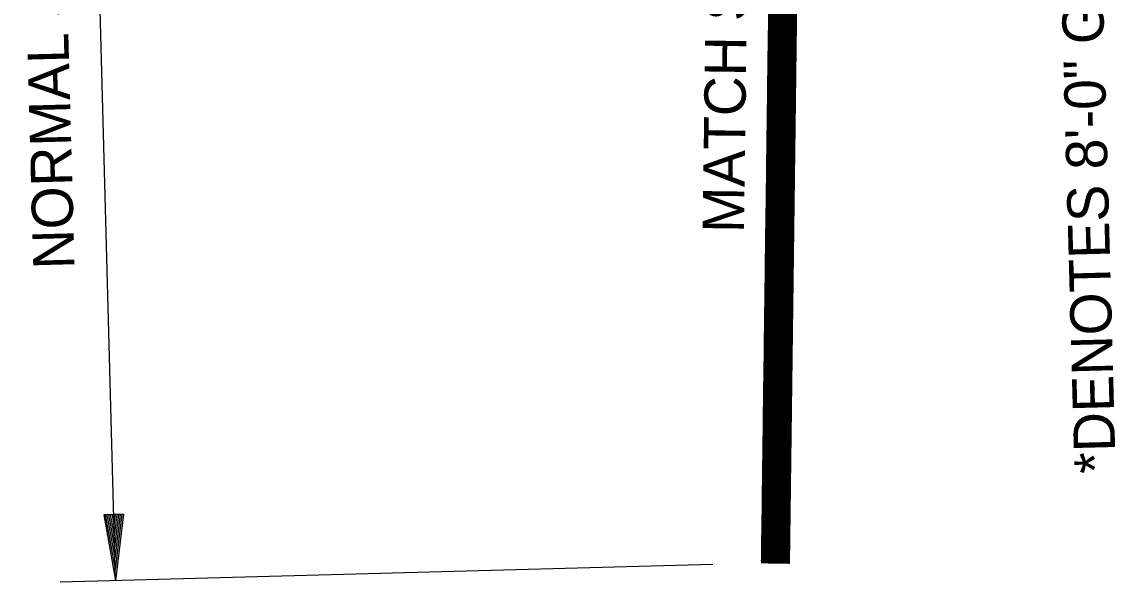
# Model space of a CAD drawing. Extents: x 1929624 to 1935547, y 596315 to 605721.
# Drawn here: x 1932254.7 to 1932413.5, y 600448.6 to 600530 of the extents above; entities that cross this region are included whole.
import ezdxf

# ---------------------------------------------------------------- set-up
doc = ezdxf.new("R2010")
doc.units = 0
doc.layers.add('Default', color=7, linetype='Continuous')
doc.layers.add('R_Draft', color=7, linetype='Continuous')

msp = doc.modelspace()

# ---------------------------------------------------------------- linework, layer by layer
at = {"layer": 'Default'}
for p, q in [((1932365.29, 600687.8), (1932362.18, 600451.38)), ((1932369.13, 600675.3), (1932366.19, 600451.33)), ((1932367.21, 600528.79), (1932365.06, 600608.88)), ((1932367.22, 600529.39), (1932365.08, 600608.9)), ((1932366.92, 600507.17), (1932364.23, 600607.39)), ((1932366.93, 600507.77), (1932364.24, 600607.99)), ((1932366.94, 600508.37), (1932364.26, 600608.04)), ((1932366.95, 600508.97), (1932364.29, 600608.07)), ((1932366.96, 600509.57), (1932364.31, 600608.09)), ((1932366.96, 600510.17), (1932364.33, 600608.12)), ((1932366.97, 600510.78), (1932364.36, 600608.14)), ((1932366.98, 600511.38), (1932364.38, 600608.17)), ((1932366.99, 600511.98), (1932364.4, 600608.19)), ((1932367, 600512.58), (1932364.43, 600608.21)), ((1932367, 600513.18), (1932364.45, 600608.24)), ((1932367.01, 600513.78), (1932364.47, 600608.26)), ((1932367.02, 600514.38), (1932364.5, 600608.29)), ((1932367.03, 600514.98), (1932364.52, 600608.31)), ((1932367.03, 600515.58), (1932364.54, 600608.34)), ((1932367.04, 600516.18), (1932364.57, 600608.36)), ((1932367.05, 600516.78), (1932364.59, 600608.39)), ((1932367.06, 600517.38), (1932364.61, 600608.41)), ((1932367.07, 600517.98), (1932364.64, 600608.44)), ((1932367.07, 600518.58), (1932364.66, 600608.46)), ((1932367.08, 600519.18), (1932364.68, 600608.49)), ((1932367.09, 600519.78), (1932364.71, 600608.51)), ((1932367.1, 600520.38), (1932364.73, 600608.53)), ((1932367.11, 600520.98), (1932364.76, 600608.56)), ((1932367.11, 600521.59), (1932364.78, 600608.58)), ((1932367.12, 600522.19), (1932364.8, 600608.61)), ((1932367.13, 600522.79), (1932364.83, 600608.63)), ((1932367.14, 600523.39), (1932364.85, 600608.66)), ((1932367.15, 600523.99), (1932364.87, 600608.68)), ((1932367.15, 600524.59), (1932364.9, 600608.71)), ((1932367.16, 600525.19), (1932364.92, 600608.73)), ((1932367.17, 600525.79), (1932364.94, 600608.76)), ((1932367.18, 600526.39), (1932364.97, 600608.78)), ((1932367.18, 600526.99), (1932364.99, 600608.81)), ((1932367.19, 600527.59), (1932365.01, 600608.83)), ((1932367.2, 600528.19), (1932365.04, 600608.86)), ((1932366.91, 600505.97), (1932364.22, 600606.19)), ((1932366.92, 600506.57), (1932364.23, 600606.79)), ((1932268.3, 600448.86), (1932264.1, 600605.33)), ((1932366.89, 600504.17), (1932364.19, 600604.39)), ((1932366.89, 600504.77), (1932364.2, 600604.99)), ((1932366.9, 600505.37), (1932364.21, 600605.59)), ((1932366.86, 600502.37), (1932364.17, 600602.59)), ((1932366.87, 600502.97), (1932364.18, 600603.19)), ((1932366.88, 600503.57), (1932364.19, 600603.79)), ((1932366.85, 600501.77), (1932364.16, 600601.99)), ((1932366.85, 600501.17), (1932364.16, 600601.39)), ((1932366.82, 600499.37), (1932364.13, 600599.58)), ((1932366.83, 600499.97), (1932364.14, 600600.18)), ((1932366.84, 600500.57), (1932364.15, 600600.78)), ((1932366.8, 600497.56), (1932364.11, 600597.78)), ((1932366.81, 600498.77), (1932364.12, 600598.98)), ((1932366.81, 600498.17), (1932364.12, 600598.38)), ((1932366.78, 600496.36), (1932364.09, 600596.58)), ((1932366.79, 600496.96), (1932364.1, 600597.18)), ((1932366.76, 600494.56), (1932364.07, 600594.78)), ((1932366.77, 600495.76), (1932364.08, 600595.98)), ((1932366.77, 600495.16), (1932364.08, 600595.38)), ((1932366.74, 600493.36), (1932364.05, 600593.58)), ((1932366.75, 600493.96), (1932364.06, 600594.18)), ((1932366.72, 600491.56), (1932364.03, 600591.78)), ((1932366.74, 600492.76), (1932364.04, 600592.98)), ((1932366.73, 600492.16), (1932364.04, 600592.38)), ((1932366.7, 600490.36), (1932364.01, 600590.57)), ((1932366.7, 600489.76), (1932364.01, 600589.97)), ((1932366.71, 600490.96), (1932364.02, 600591.18)), ((1932366.68, 600488.56), (1932363.99, 600588.77)), ((1932366.69, 600489.16), (1932364, 600589.37)), ((1932366.66, 600487.36), (1932363.97, 600587.57)), ((1932366.66, 600486.76), (1932363.97, 600586.97)), ((1932366.67, 600487.96), (1932363.98, 600588.17)), ((1932366.63, 600484.95), (1932363.94, 600585.17)), ((1932366.64, 600485.55), (1932363.95, 600585.77)), ((1932366.65, 600486.16), (1932363.96, 600586.37)), ((1932366.62, 600484.35), (1932363.93, 600584.57)), ((1932366.62, 600483.75), (1932363.93, 600583.97)), ((1932366.59, 600481.95), (1932363.9, 600582.17)), ((1932366.6, 600482.55), (1932363.91, 600582.77)), ((1932366.61, 600483.15), (1932363.92, 600583.37)), ((1932366.57, 600480.15), (1932363.88, 600580.37)), ((1932366.59, 600481.35), (1932363.89, 600581.57)), ((1932366.58, 600480.75), (1932363.89, 600580.97)), ((1932366.55, 600478.95), (1932363.86, 600579.17)), ((1932366.56, 600479.55), (1932363.87, 600579.77)), ((1932366.53, 600477.15), (1932363.84, 600577.37)), ((1932366.54, 600477.75), (1932363.85, 600577.97)), ((1932366.55, 600478.35), (1932363.86, 600578.57)), ((1932366.51, 600475.95), (1932363.82, 600576.16)), ((1932366.51, 600475.35), (1932363.82, 600575.56)), ((1932366.52, 600476.55), (1932363.83, 600576.77)), ((1932366.49, 600474.14), (1932363.8, 600574.36)), ((1932366.5, 600474.74), (1932363.81, 600574.96)), ((1932366.47, 600472.94), (1932363.78, 600573.16)), ((1932366.47, 600472.34), (1932363.78, 600572.56)), ((1932366.48, 600473.54), (1932363.79, 600573.76)), ((1932366.44, 600470.54), (1932363.75, 600570.76)), ((1932366.45, 600471.14), (1932363.76, 600571.36)), ((1932366.46, 600471.74), (1932363.77, 600571.96)), ((1932366.43, 600469.34), (1932363.74, 600569.56)), ((1932366.44, 600469.94), (1932363.75, 600570.16)), ((1932366.4, 600467.54), (1932363.71, 600567.76)), ((1932366.41, 600468.14), (1932363.72, 600568.36)), ((1932366.42, 600468.74), (1932363.73, 600568.96)), ((1932366.39, 600466.34), (1932363.7, 600566.56)), ((1932366.4, 600466.94), (1932363.71, 600567.16)), ((1932366.36, 600464.54), (1932363.67, 600564.75)), ((1932366.37, 600465.14), (1932363.68, 600565.35)), ((1932366.38, 600465.74), (1932363.69, 600565.95)), ((1932366.34, 600462.74), (1932363.65, 600562.95)), ((1932366.35, 600463.34), (1932363.66, 600563.55)), ((1932366.36, 600463.94), (1932363.67, 600564.15)), ((1932366.32, 600461.54), (1932363.63, 600561.75)), ((1932366.33, 600462.14), (1932363.64, 600562.35)), ((1932366.3, 600459.73), (1932363.61, 600559.95)), ((1932366.31, 600460.33), (1932363.62, 600560.55)), ((1932366.32, 600460.93), (1932363.63, 600561.15)), ((1932366.28, 600457.93), (1932363.59, 600558.15)), ((1932366.29, 600459.13), (1932363.6, 600559.35)), ((1932366.29, 600458.53), (1932363.6, 600558.75)), ((1932366.26, 600456.73), (1932363.57, 600556.95)), ((1932366.27, 600457.33), (1932363.58, 600557.55)), ((1932366.24, 600454.93), (1932363.55, 600555.15)), ((1932366.25, 600456.13), (1932363.56, 600556.35)), ((1932366.25, 600455.53), (1932363.56, 600555.75)), ((1932366.21, 600453.13), (1932363.52, 600553.34)), ((1932366.22, 600453.73), (1932363.53, 600553.94)), ((1932366.23, 600454.33), (1932363.54, 600554.55)), ((1932366.2, 600451.93), (1932363.51, 600552.14)), ((1932366.21, 600452.53), (1932363.52, 600552.74)), ((1932366.14, 600451.33), (1932363.48, 600550.34)), ((1932366.17, 600451.32), (1932363.49, 600550.94)), ((1932366.19, 600451.33), (1932363.5, 600551.54)), ((1932366.07, 600451.33), (1932363.46, 600548.54)), ((1932366.09, 600451.33), (1932363.47, 600549.14)), ((1932366.12, 600451.33), (1932363.48, 600549.74)), ((1932366.05, 600451.33), (1932363.45, 600547.94)), ((1932366.02, 600451.33), (1932363.45, 600547.34)), ((1932365.95, 600451.33), (1932363.42, 600545.54)), ((1932365.97, 600451.33), (1932363.43, 600546.14)), ((1932366, 600451.33), (1932363.44, 600546.74)), ((1932365.93, 600451.33), (1932363.41, 600544.94)), ((1932365.9, 600451.33), (1932363.41, 600544.34)), ((1932365.83, 600451.33), (1932363.38, 600542.54)), ((1932365.85, 600451.33), (1932363.39, 600543.14)), ((1932365.88, 600451.33), (1932363.4, 600543.74)), ((1932365.76, 600451.33), (1932363.36, 600540.73)), ((1932365.81, 600451.33), (1932363.37, 600541.94)), ((1932365.78, 600451.33), (1932363.37, 600541.34)), ((1932365.71, 600451.33), (1932363.34, 600539.53)), ((1932365.73, 600451.33), (1932363.35, 600540.13)), ((1932365.64, 600451.33), (1932363.32, 600537.73)), ((1932365.69, 600451.33), (1932363.33, 600538.93)), ((1932365.66, 600451.33), (1932363.33, 600538.33)), ((1932365.59, 600451.33), (1932363.3, 600536.53)), ((1932365.57, 600451.33), (1932363.3, 600535.93)), ((1932365.61, 600451.33), (1932363.31, 600537.13)), ((1932365.52, 600451.33), (1932363.28, 600534.73)), ((1932365.54, 600451.33), (1932363.29, 600535.33)), ((1932365.47, 600451.34), (1932363.26, 600533.53)), ((1932365.45, 600451.33), (1932363.26, 600532.93)), ((1932365.49, 600451.34), (1932363.27, 600534.13)), ((1932365.37, 600451.34), (1932363.23, 600531.13)), ((1932365.4, 600451.34), (1932363.24, 600531.73)), ((1932365.42, 600451.34), (1932363.25, 600532.33)), ((1932365.35, 600451.34), (1932363.22, 600530.52)), ((1932365.33, 600451.34), (1932363.22, 600529.92)), ((1932365.25, 600451.34), (1932363.19, 600528.12)), ((1932365.28, 600451.34), (1932363.2, 600528.72)), ((1932365.3, 600451.34), (1932363.21, 600529.32)), ((1932365.18, 600451.34), (1932363.17, 600526.32)), ((1932365.21, 600451.34), (1932363.18, 600526.92)), ((1932365.23, 600451.34), (1932363.19, 600527.52)), ((1932365.13, 600451.34), (1932363.15, 600525.12)), ((1932365.16, 600451.34), (1932363.16, 600525.72)), ((1932365.06, 600451.34), (1932363.13, 600523.32)), ((1932365.09, 600451.34), (1932363.14, 600523.92)), ((1932365.11, 600451.34), (1932363.15, 600524.52)), ((1932365.01, 600451.34), (1932363.11, 600522.12)), ((1932364.99, 600451.34), (1932363.11, 600521.52)), ((1932365.04, 600451.34), (1932363.12, 600522.72)), ((1932364.94, 600451.34), (1932363.09, 600520.32)), ((1932364.97, 600451.34), (1932363.1, 600520.92)), ((1932364.89, 600451.34), (1932363.07, 600519.12)), ((1932364.87, 600451.34), (1932363.07, 600518.52)), ((1932364.92, 600451.34), (1932363.08, 600519.72)), ((1932364.82, 600451.34), (1932363.05, 600517.32)), ((1932364.85, 600451.34), (1932363.06, 600517.92)), ((1932364.75, 600451.34), (1932363.03, 600515.51)), ((1932364.8, 600451.34), (1932363.04, 600516.72)), ((1932364.77, 600451.35), (1932363.04, 600516.11)), ((1932364.68, 600451.35), (1932363, 600513.71)), ((1932364.7, 600451.35), (1932363.01, 600514.31)), ((1932364.73, 600451.35), (1932363.02, 600514.91)), ((1932364.63, 600451.35), (1932362.99, 600512.51)), ((1932364.65, 600451.35), (1932363, 600513.11)), ((1932364.56, 600451.35), (1932362.96, 600510.71)), ((1932364.58, 600451.35), (1932362.97, 600511.31)), ((1932364.61, 600451.35), (1932362.98, 600511.91)), ((1932364.49, 600451.35), (1932362.94, 600508.91)), ((1932364.51, 600451.35), (1932362.95, 600509.51)), ((1932364.53, 600451.35), (1932362.96, 600510.11)), ((1932364.44, 600451.35), (1932362.92, 600507.71)), ((1932364.46, 600451.35), (1932362.93, 600508.31)), ((1932364.37, 600451.35), (1932362.9, 600505.91)), ((1932364.39, 600451.35), (1932362.91, 600506.51)), ((1932364.41, 600451.35), (1932362.92, 600507.11)), ((1932364.29, 600451.35), (1932362.88, 600504.1)), ((1932364.34, 600451.35), (1932362.89, 600505.3)), ((1932364.32, 600451.35), (1932362.89, 600504.7)), ((1932364.25, 600451.35), (1932362.86, 600502.9)), ((1932364.27, 600451.35), (1932362.87, 600503.5)), ((1932364.17, 600451.35), (1932362.84, 600501.1)), ((1932364.22, 600451.35), (1932362.85, 600502.3)), ((1932364.2, 600451.35), (1932362.85, 600501.7)), ((1932364.1, 600451.35), (1932362.81, 600499.3)), ((1932364.13, 600451.35), (1932362.82, 600499.9)), ((1932364.15, 600451.35), (1932362.83, 600500.5)), ((1932364.05, 600451.35), (1932362.8, 600498.1)), ((1932364.08, 600451.35), (1932362.81, 600498.7)), ((1932363.98, 600451.36), (1932362.77, 600496.3)), ((1932364.01, 600451.36), (1932362.78, 600496.9)), ((1932364.03, 600451.35), (1932362.79, 600497.5)), ((1932363.93, 600451.36), (1932362.76, 600495.09)), ((1932363.96, 600451.35), (1932362.77, 600495.7)), ((1932363.89, 600451.36), (1932362.74, 600493.89)), ((1932363.86, 600451.36), (1932362.74, 600493.29)), ((1932363.91, 600451.36), (1932362.75, 600494.49)), ((1932363.79, 600451.36), (1932362.71, 600491.49)), ((1932363.81, 600451.36), (1932362.72, 600492.09)), ((1932363.84, 600451.36), (1932362.73, 600492.69)), ((1932363.77, 600451.36), (1932362.7, 600490.89)), ((1932363.74, 600451.36), (1932362.7, 600490.29)), ((1932363.67, 600451.36), (1932362.67, 600488.49)), ((1932363.69, 600451.36), (1932362.68, 600489.09)), ((1932363.72, 600451.36), (1932362.69, 600489.69)), ((1932363.6, 600451.36), (1932362.65, 600486.69)), ((1932363.64, 600451.36), (1932362.66, 600487.89)), ((1932363.62, 600451.36), (1932362.66, 600487.29)), ((1932363.55, 600451.36), (1932362.63, 600485.49)), ((1932363.57, 600451.36), (1932362.64, 600486.09)), ((1932363.48, 600451.36), (1932362.61, 600483.69)), ((1932363.52, 600451.36), (1932362.62, 600484.89)), ((1932363.5, 600451.36), (1932362.62, 600484.29)), ((1932363.43, 600451.36), (1932362.59, 600482.49)), ((1932363.4, 600451.36), (1932362.59, 600481.89)), ((1932363.45, 600451.36), (1932362.6, 600483.09)), ((1932363.36, 600451.36), (1932362.57, 600480.68)), ((1932363.38, 600451.36), (1932362.58, 600481.29)), ((1932363.31, 600451.36), (1932362.55, 600479.48)), ((1932363.28, 600451.37), (1932362.55, 600478.88)), ((1932363.33, 600451.36), (1932362.56, 600480.08)), ((1932363.21, 600451.37), (1932362.52, 600477.08)), ((1932363.24, 600451.36), (1932362.53, 600477.68)), ((1932363.26, 600451.36), (1932362.54, 600478.28)), ((1932363.19, 600451.37), (1932362.51, 600476.48)), ((1932363.16, 600451.37), (1932362.51, 600475.88)), ((1932363.09, 600451.37), (1932362.48, 600474.08)), ((1932363.12, 600451.37), (1932362.49, 600474.68)), ((1932363.14, 600451.37), (1932362.5, 600475.28)), ((1932363.02, 600451.37), (1932362.46, 600472.28)), ((1932363.04, 600451.37), (1932362.47, 600472.88)), ((1932363.07, 600451.37), (1932362.48, 600473.48)), ((1932362.97, 600451.37), (1932362.44, 600471.08)), ((1932363, 600451.37), (1932362.45, 600471.68)), ((1932362.9, 600451.37), (1932362.42, 600469.27)), ((1932362.92, 600451.37), (1932362.43, 600469.87)), ((1932362.95, 600451.37), (1932362.44, 600470.47)), ((1932362.85, 600451.37), (1932362.4, 600468.07)), ((1932362.88, 600451.37), (1932362.41, 600468.67)), ((1932362.78, 600451.37), (1932362.38, 600466.27)), ((1932362.8, 600451.37), (1932362.39, 600466.87)), ((1932362.83, 600451.37), (1932362.4, 600467.47)), ((1932362.73, 600451.37), (1932362.36, 600465.07)), ((1932362.71, 600451.37), (1932362.36, 600464.47)), ((1932362.76, 600451.37), (1932362.37, 600465.67)), ((1932362.66, 600451.37), (1932362.34, 600463.27)), ((1932362.68, 600451.37), (1932362.35, 600463.87)), ((1932362.59, 600451.37), (1932362.32, 600461.47)), ((1932362.64, 600451.37), (1932362.33, 600462.67)), ((1932362.61, 600451.37), (1932362.33, 600462.07)), ((1932362.52, 600451.37), (1932362.29, 600459.66)), ((1932362.54, 600451.37), (1932362.3, 600460.27)), ((1932362.56, 600451.37), (1932362.31, 600460.87)), ((1932269.48, 600458.49), (1932266.6, 600458.42)), ((1932266.6, 600458.42), (1932268.3, 600448.86)), ((1932266.84, 600458.42), (1932268.26, 600450.47)), ((1932267.08, 600458.43), (1932268.21, 600452.12)), ((1932267.32, 600458.44), (1932268.17, 600453.7)), ((1932267.56, 600458.44), (1932268.13, 600455.34)), ((1932267.83, 600458.45), (1932268.08, 600456.94)), ((1932268.26, 600458.46), (1932268.08, 600456.94)), ((1932268.5, 600458.47), (1932268.13, 600455.34)), ((1932268.76, 600458.47), (1932268.17, 600453.7)), ((1932269, 600458.48), (1932268.21, 600452.12)), ((1932269.24, 600458.49), (1932268.26, 600450.47)), ((1932269.48, 600458.49), (1932268.3, 600448.86)), ((1932362.47, 600451.37), (1932362.28, 600458.46)), ((1932362.49, 600451.38), (1932362.29, 600459.06)), ((1932362.4, 600451.38), (1932362.25, 600456.66)), ((1932362.42, 600451.38), (1932362.26, 600457.26)), ((1932362.44, 600451.38), (1932362.27, 600457.86)), ((1932362.32, 600451.38), (1932362.23, 600454.86)), ((1932362.35, 600451.38), (1932362.24, 600455.46)), ((1932362.37, 600451.38), (1932362.25, 600456.06)), ((1932362.28, 600451.38), (1932362.21, 600453.66)), ((1932362.3, 600451.38), (1932362.22, 600454.26)), ((1932362.2, 600451.38), (1932362.19, 600451.86)), ((1932362.23, 600451.38), (1932362.2, 600452.46)), ((1932362.25, 600451.38), (1932362.21, 600453.06)), ((1932355.1, 600451.19), (1932260.26, 600448.64))]:
    msp.add_line(p, q, dxfattribs=at)

# ---------------------------------------------------------------- texts
msp.add_text('*DENOTES 8\'-0" GUARDRAIL', height=6, rotation=91.5377, dxfattribs=at).set_placement((1932413.64, 600464.48))
at = {"layer": 'R_Draft'}
for s, rotation, p in [('MATCH SHLDR. SLOPE', 89.2467, (1932359.61, 600499.3)), ('NORMAL SHLDR.', 91.5377, (1932262.38, 600494.13))]:
    msp.add_text(s, height=6, rotation=rotation, dxfattribs=at).set_placement(p)

doc.saveas('drawing.dxf')
